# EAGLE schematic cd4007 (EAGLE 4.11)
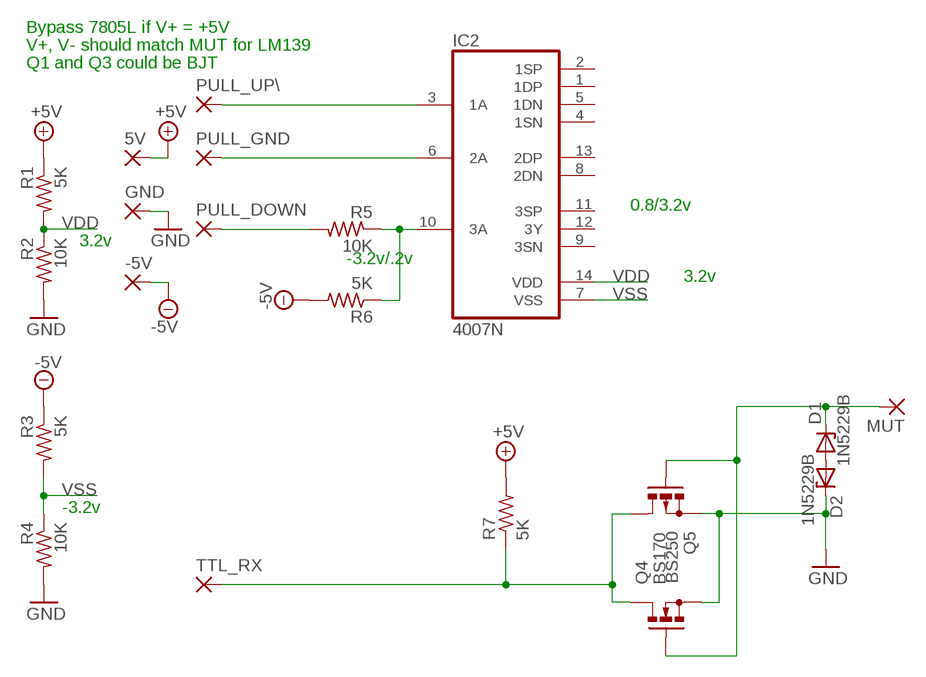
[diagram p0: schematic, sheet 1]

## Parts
5V  1,6/0,9  [1,6/0,9]
-5V  1,6/0,9  [1,6/0,9]
D1  1N5229B  ZENER-DIODEDO35Z10  [DO35Z10]
D2  1N5229B  ZENER-DIODEDO35Z10  [DO35Z10]
GND  1,6/0,9  [1,6/0,9]
IC2  4007N  [DIL14]
MUT  1,6/0,9  [1,6/0,9]
PULL_DOWN  1,6/0,9  [1,6/0,9]
PULL_GND  1,6/0,9  [1,6/0,9]
PULL_UP\  1,6/0,9  [1,6/0,9]
Q4  BS170  [SOT54E]
Q5  BS250  [SOT54E]
R1  5K  R-US_0207/10  [0207/10]
R2  10K  R-US_0207/10  [0207/10]
R3  5K  R-US_0207/10  [0207/10]
R4  10K  R-US_0207/10  [0207/10]
R5  10K  R-US_0207/10  [0207/10]
R6  5K  R-US_0207/10  [0207/10]
R7  5K  R-US_0207/10  [0207/10]
TTL_RX  1,6/0,9  [1,6/0,9]

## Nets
+5V: 5V.1(P) R1.1 R7.2
-5V: -5V.1(P) R3.1 R6.2
GND: D2.C GND.1(P) Q4.S Q5.S R2.2 R4.2
N$1: D1.C MUT.1(P) Q4.G Q5.G
N$2: IC2.10(3A) R5.1 R6.1
N$3: IC2.6(2A) PULL_GND.1(P)
N$4: PULL_DOWN.1(P) R5.2
N$7: D1.A D2.A
N$8: Q4.D Q5.D R7.1 TTL_RX.1(P)
N$10: IC2.3(1A) PULL_UP\.1(P)
VDD: IC2.14(VDD) R1.2 R2.1
VSS: IC2.7(VSS) R3.2 R4.1
Unconnected: IC2.1(1DP) IC2.2(1SP) IC2.4(1SN) IC2.5(1DN) IC2.8(2DN) IC2.9(3SN) IC2.11(3SP) IC2.12(3Y) IC2.13(2DP)

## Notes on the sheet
- Bypass 7805L if V+ = +5V
- V+, V- should match MUT for LM139
- Q1 and Q3 could be BJT
- 0.8/3.2v
- 3.2v
- -3.2v/.2v
- 3.2v
- -3.2v

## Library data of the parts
5V -5V GND MUT PULL_DOWN PULL_GND PULL_UP\ TTL_RX = wirepad:1,6/0,9: THROUGH-HOLE PAD
D1 D2 = diode:ZENER-DIODE: Z-Diode
IC2 = 40xx:4007: Dual COMPLIMENTARY PAIR plus INVERTER
Q4 = transistor-small-signal:BS170: N-CHANNEL MOS FET
Q5 = transistor-small-signal:BS250: P-CHANNEL MOS FET
R1-R7 = rcl:R-US_: RESISTOR, American symbol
